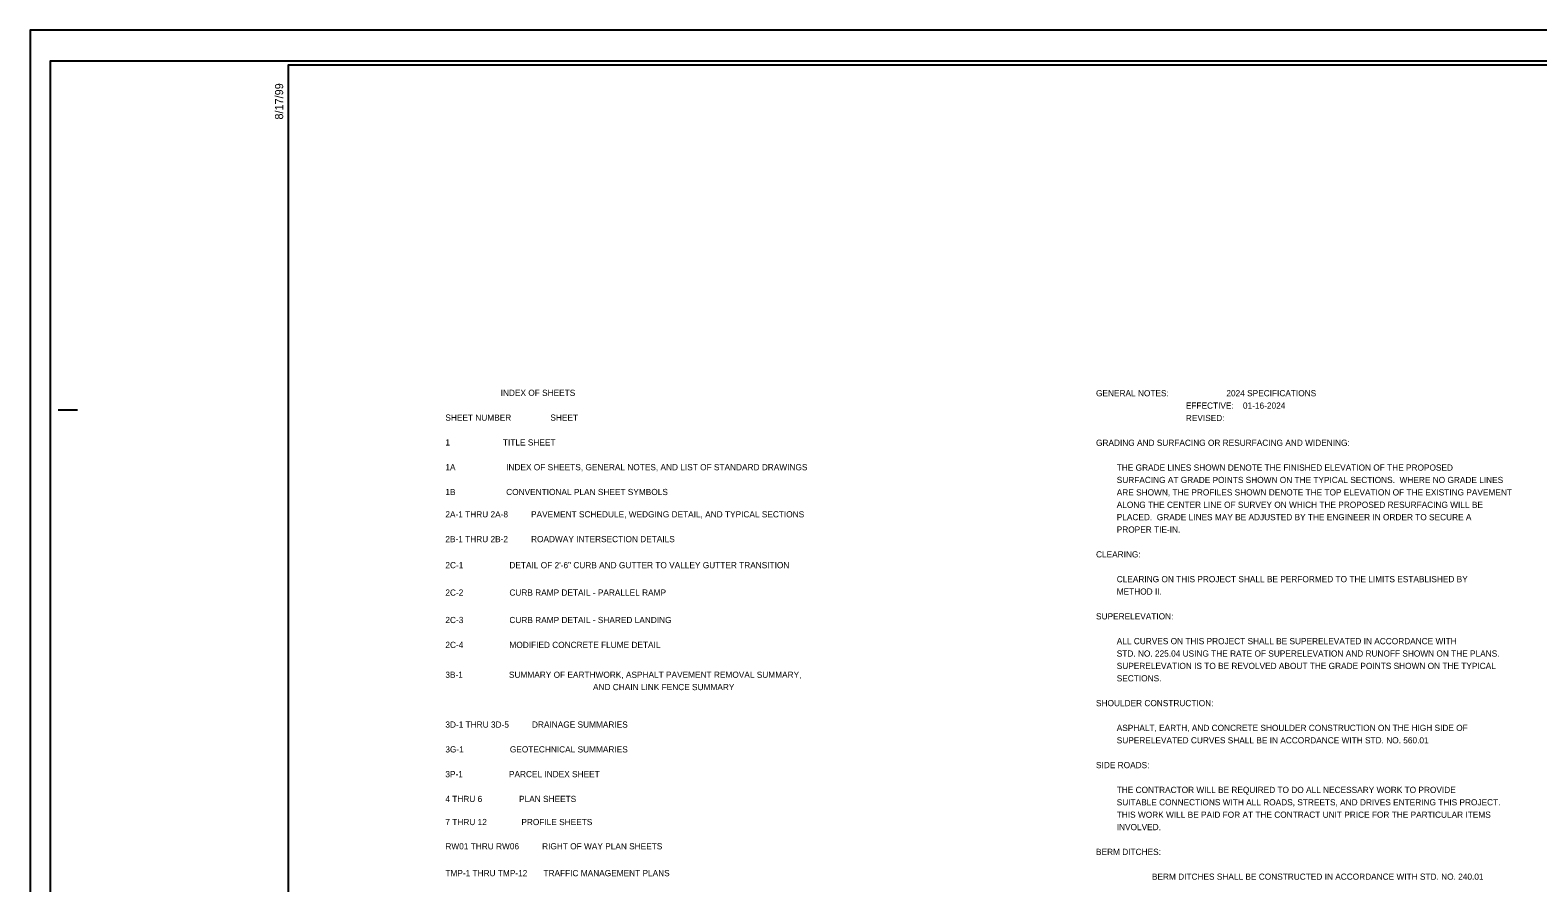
# Model space of a CAD drawing. Extents: x 1537922 to 1539606, y 409903 to 410998.
# Drawn here: x 1537922 to 1538895, y 410448 to 410998 of the extents above; entities that cross this region are included whole.
import ezdxf

# ---------------------------------------------------------------- set-up
doc = ezdxf.new("R2010")
doc.units = 0
for name, color, linetype in [('Default', 7, 'Continuous'), ('Sheet Cutting Line CELL', 7, 'Continuous'), ('Sheet Plan CELL', 7, 'Continuous'), ('Sheet Plot Border Inside CELL', 7, 'Continuous'), ('Sheet Plot Border Outside CELL', 7, 'Continuous')]:
    doc.layers.add(name, color=color, linetype=linetype)

msp = doc.modelspace()

# ---------------------------------------------------------------- linework, layer by layer
at = {"layer": 'Sheet Cutting Line CELL'}
for p, q in [((1539605.87, 410998.35), (1537922.37, 410998.35)), ((1537922.37, 410998.35), (1537922.37, 409903.35))]:
    msp.add_line(p, q, dxfattribs=at)
at = {"layer": 'Sheet Plan CELL'}
for p, q in [((1538088.87, 410975.85), (1538088.87, 410975.85)), ((1537940.37, 410753.35), (1537952.87, 410753.35))]:
    msp.add_line(p, q, dxfattribs=at)
msp.add_lwpolyline([(1539588.87, 410975.85), (1538088.87, 410975.85), (1538088.87, 409925.85), (1539588.87, 409925.85)], close=True, dxfattribs=at)
at = {"layer": 'Sheet Plot Border Inside CELL'}
msp.add_lwpolyline([(1537935.37, 409923.35), (1539601.37, 409923.35), (1539601.37, 410978.35), (1537935.37, 410978.35)], close=True, dxfattribs=at)
at = {"layer": 'Sheet Plot Border Outside CELL'}
msp.add_lwpolyline([(1537922.37, 409903.35), (1539605.87, 409903.35), (1539605.87, 410998.35), (1537922.37, 410998.35)], close=True, dxfattribs=at)

# ---------------------------------------------------------------- texts
at = {"layer": 'Default'}
for s, p in [('                        INDEX OF SHEETS ', (1538190.28, 410762.31)), ('GENERAL NOTES:                         2024 SPECIFICATIONS', (1538610.1, 410762.07)), ('                                       EFFECTIVE:    01-16-2024', (1538610.1, 410754.07)), ('SHEET NUMBER                 SHEET   ', (1538190.28, 410746.31)), ('                                       REVISED:      ', (1538610.1, 410746.07)), ('1                       TITLE SHEET', (1538190.28, 410730.31)), ('GRADING AND SURFACING OR RESURFACING AND WIDENING:  ', (1538610.1, 410730.07)), ('1A                      INDEX OF SHEETS, GENERAL NOTES, AND LIST OF STANDARD DRAWINGS', (1538190.28, 410714.31)), ('         THE GRADE LINES SHOWN DENOTE THE FINISHED ELEVATION OF THE PROPOSED ', (1538610.1, 410714.07)), ('         SURFACING AT GRADE POINTS SHOWN ON THE TYPICAL SECTIONS.  WHERE NO GRADE LINES ', (1538610.1, 410706.07)), ('1B                      CONVENTIONAL PLAN SHEET SYMBOLS ', (1538190.28, 410698.31)), ('         ARE SHOWN, THE PROFILES SHOWN DENOTE THE TOP ELEVATION OF THE EXISTING PAVEMENT ', (1538610.1, 410698.07)), ('2A-1 THRU 2A-8          PAVEMENT SCHEDULE, WEDGING DETAIL, AND TYPICAL SECTIONS', (1538190.28, 410683.91)), ('         ALONG THE CENTER LINE OF SURVEY ON WHICH THE PROPOSED RESURFACING WILL BE ', (1538610.1, 410690.07)), ('         PLACED.  GRADE LINES MAY BE ADJUSTED BY THE ENGINEER IN ORDER TO SECURE A ', (1538610.1, 410682.07)), ('         PROPER TIE-IN.  ', (1538610.1, 410674.07)), ('2B-1 THRU 2B-2          ROADWAY INTERSECTION DETAILS', (1538190.28, 410667.91)), ('CLEARING:  ', (1538610.1, 410658.07)), ('2C-1                    DETAIL OF 2\'-6" CURB AND GUTTER TO VALLEY GUTTER TRANSITION ', (1538190.28, 410651.09)), ('         CLEARING ON THIS PROJECT SHALL BE PERFORMED TO THE LIMITS ESTABLISHED BY ', (1538610.1, 410642.07)), ('2C-2                    CURB RAMP DETAIL - PARALLEL RAMP', (1538190.28, 410633.4)), ('         METHOD II.', (1538610.1, 410634.07)), ('2C-3                    CURB RAMP DETAIL - SHARED LANDING', (1538190.28, 410615.7)), ('SUPERELEVATION:  ', (1538610.1, 410618.07)), ('2C-4                    MODIFIED CONCRETE FLUME DETAIL', (1538190.28, 410599.65)), ('         ALL CURVES ON THIS PROJECT SHALL BE SUPERELEVATED IN ACCORDANCE WITH', (1538610.1, 410602.07)), ('         STD. NO. 225.04 USING THE RATE OF SUPERELEVATION AND RUNOFF SHOWN ON THE PLANS.', (1538610.1, 410594.07)), ('         SUPERELEVATION IS TO BE REVOLVED ABOUT THE GRADE POINTS SHOWN ON THE TYPICAL ', (1538610.1, 410586.07)), ('3B-1                    SUMMARY OF EARTHWORK, ASPHALT PAVEMENT REMOVAL SUMMARY, ', (1538190.28, 410580.38)), ('         SECTIONS.  ', (1538610.1, 410578.07)), ('AND CHAIN LINK FENCE SUMMARY ', (1538285.53, 410572.43)), ('SHOULDER CONSTRUCTION:  ', (1538610.1, 410562.07)), ('3D-1 THRU 3D-5          DRAINAGE SUMMARIES', (1538190.28, 410548.23)), ('         ASPHALT, EARTH, AND CONCRETE SHOULDER CONSTRUCTION ON THE HIGH SIDE OF', (1538610.1, 410546.07)), ('         SUPERELEVATED CURVES SHALL BE IN ACCORDANCE WITH STD. NO. 560.01', (1538610.1, 410538.07)), ('3G-1                    GEOTECHNICAL SUMMARIES', (1538190.28, 410532.23)), ('3P-1                    PARCEL INDEX SHEET', (1538190.28, 410516.23)), ('SIDE ROADS:  ', (1538610.1, 410522.07)), ('         THE CONTRACTOR WILL BE REQUIRED TO DO ALL NECESSARY WORK TO PROVIDE ', (1538610.1, 410506.07)), ('4 THRU 6                PLAN SHEETS', (1538190.28, 410500.23)), ('         SUITABLE CONNECTIONS WITH ALL ROADS, STREETS, AND DRIVES ENTERING THIS PROJECT.  ', (1538610.1, 410498.07)), ('         THIS WORK WILL BE PAID FOR AT THE CONTRACT UNIT PRICE FOR THE PARTICULAR ITEMS ', (1538610.1, 410490.07)), ('7 THRU 12               PROFILE SHEETS', (1538190.28, 410485.33)), ('         INVOLVED.  ', (1538610.1, 410482.07)), ('RW01 THRU RW06          RIGHT OF WAY PLAN SHEETS', (1538190.28, 410469.68)), ('BERM DITCHES:', (1538610.1, 410466.07)), ('TMP-1 THRU TMP-12       TRAFFIC MANAGEMENT PLANS', (1538190.28, 410452.34)), ('BERM DITCHES SHALL BE CONSTRUCTED IN ACCORDANCE WITH STD. NO. 240.01', (1538646.16, 410450.07))]:
    msp.add_text(s, height=4, dxfattribs=at).set_placement(p)
at = {"layer": 'Sheet Plan CELL'}
msp.add_text('8/17/99', height=5.25, rotation=90, dxfattribs=at).set_placement((1538085.62, 410940.65))

doc.saveas('drawing.dxf')
